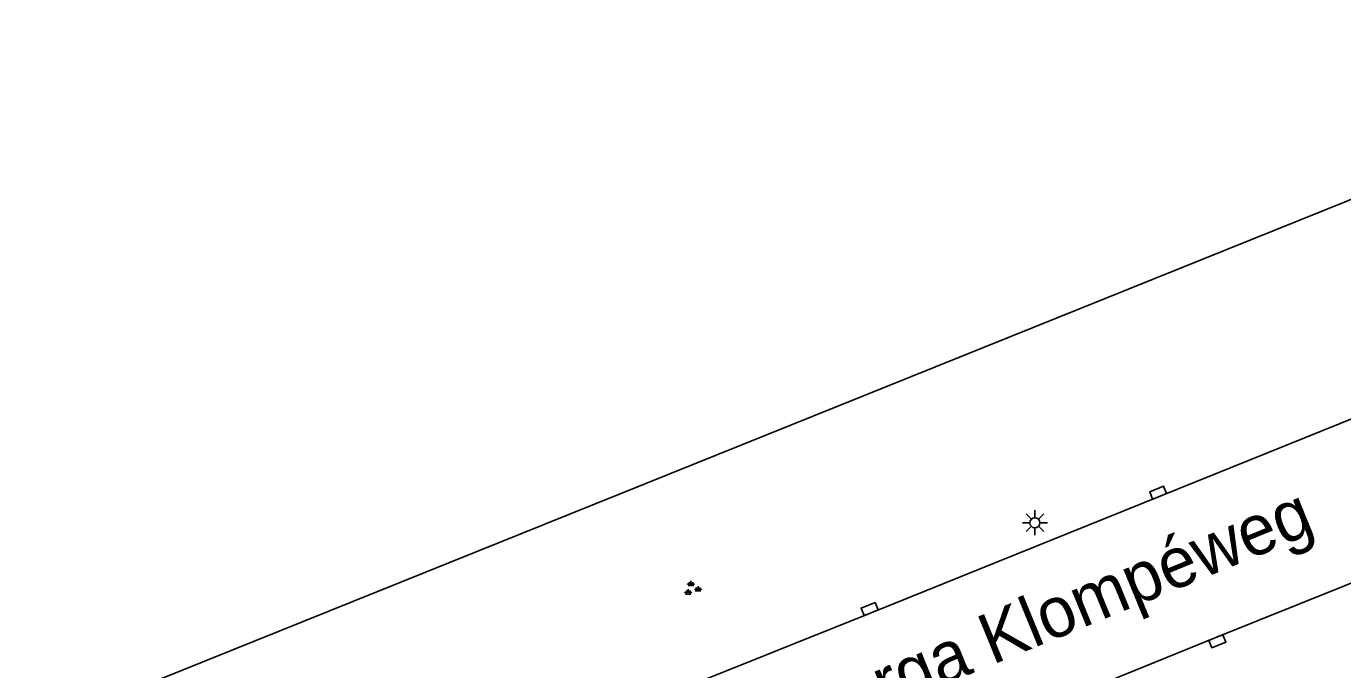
# Model space of a CAD drawing. Extents: x 126000 to 131009, y 393000 to 395500.
# Drawn here: x 130444.5 to 130510, y 394018 to 394050 of the extents above; entities that cross this region are included whole.
import ezdxf

# ---------------------------------------------------------------- set-up
doc = ezdxf.new("R2010")
doc.units = 0
for name, color, linetype in [('gg-anno-openbare ruimte label', 7, 'Continuous'), ('gg-bbg-hoofdgebouw', 7, 'Continuous'), ('gg-knt-verharding', 7, 'Continuous'), ('gt-symb-groenvak', 7, 'Continuous'), ('gt-symb-kolk', 7, 'Continuous'), ('gt-symb-lichtmast', 7, 'Continuous')]:
    doc.layers.add(name, color=color, linetype=linetype)

# ---------------------------------------------------------------- blocks, each defined once
blk = doc.blocks.new('gt0-KOLK')
at = {"layer": 'gt-symb-kolk'}
blk.add_lwpolyline([(0, 0), (0.375, 0), (0.375, 0.4), (-0.375, 0.4), (-0.375, 0), (0, 0)], dxfattribs=at)
blk = doc.blocks.new('gt0-GRVAK')
at = {"layer": 'gt-symb-groenvak'}
for p, q in [((-0.11, 0.189), (-0.228, 0.24)), ((-0.182, 0.153), (0.088, 0.153)), ((-0.091, 0.211), (-0.156, 0.322)), ((-0.047, 0.214), (-0.047, 0.393)), ((-0.004, 0.211), (0.061, 0.322)), ((0.015, 0.189), (0.133, 0.24)), ((0.262, -0.052), (0.197, 0.059)), ((0.305, -0.049), (0.305, 0.13)), ((0.349, -0.052), (0.414, 0.059)), ((-0.245, -0.228), (-0.363, -0.177)), ((-0.318, -0.264), (-0.047, -0.264)), ((-0.226, -0.206), (-0.291, -0.095)), ((-0.183, -0.203), (-0.183, -0.024)), ((-0.139, -0.206), (-0.074, -0.095)), ((-0.12, -0.228), (-0.002, -0.177)), ((0.243, -0.074), (0.125, -0.023)), ((0.17, -0.11), (0.441, -0.11)), ((0.368, -0.074), (0.486, -0.023))]:
    blk.add_line(p, q, dxfattribs=at)
blk = doc.blocks.new('gt0-LMAST')
at = {"layer": 'gt-symb-lichtmast'}
for p, q in [((-0.182, 0.173), (-0.447, 0.438)), ((-0.005, 0.246), (-0.005, 0.621)), ((0.172, 0.173), (0.437, 0.438)), ((-0.255, -0.004), (-0.63, -0.004)), ((-0.182, -0.181), (-0.447, -0.446)), ((-0.005, -0.254), (-0.005, -0.629)), ((0.437, -0.446), (0.172, -0.181)), ((0.245, -0.004), (0.62, -0.004))]:
    blk.add_line(p, q, dxfattribs=at)
blk.add_circle((-0.005, -0.004), 0.25, dxfattribs=at)

msp = doc.modelspace()

# ---------------------------------------------------------------- linework, layer by layer
at = {"layer": 'gg-bbg-hoofdgebouw'}
msp.add_line((130531.777, 394049.958), (130444.499, 394014.826), dxfattribs=at)
at = {"layer": 'gg-knt-verharding'}
for points in [[(130449.61, 394005.902), (130472.166, 394015.046), (130486.522, 394020.793), (130515.199, 394032.369), (130522.337, 394035.451), (130529.397, 394038.706), (130533.458, 394040.809), (130537.476, 394042.992)], [(130512.101, 394022.943), (130503.677, 394019.564), (130489.289, 394013.718), (130474.943, 394007.991), (130464.67, 394003.84)]]:
    msp.add_lwpolyline(points, dxfattribs=at)

# ---------------------------------------------------------------- block references
at = {"layer": 'gt-symb-groenvak'}
msp.add_blockref('gt0-GRVAK', (130477.611, 394021.99), dxfattribs=at)
at = {"layer": 'gt-symb-kolk'}
for p, rotation in [((130500.881, 394026.58), 21.897150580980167), ((130486.522, 394020.793), 21.950284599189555), ((130503.677, 394019.564), -157.92205836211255)]:
    msp.add_blockref('gt0-KOLK', p, dxfattribs=dict(at, rotation=rotation))
at = {"layer": 'gt-symb-lichtmast'}
msp.add_blockref('gt0-LMAST', (130494.68, 394025.275), dxfattribs=at)

# ---------------------------------------------------------------- texts
at = {"layer": 'gg-anno-openbare ruimte label'}
msp.add_text('Marga Klompéweg', height=2.5, rotation=22.3, dxfattribs=at).set_placement((130482.924, 394014.245))

doc.saveas('drawing.dxf')
